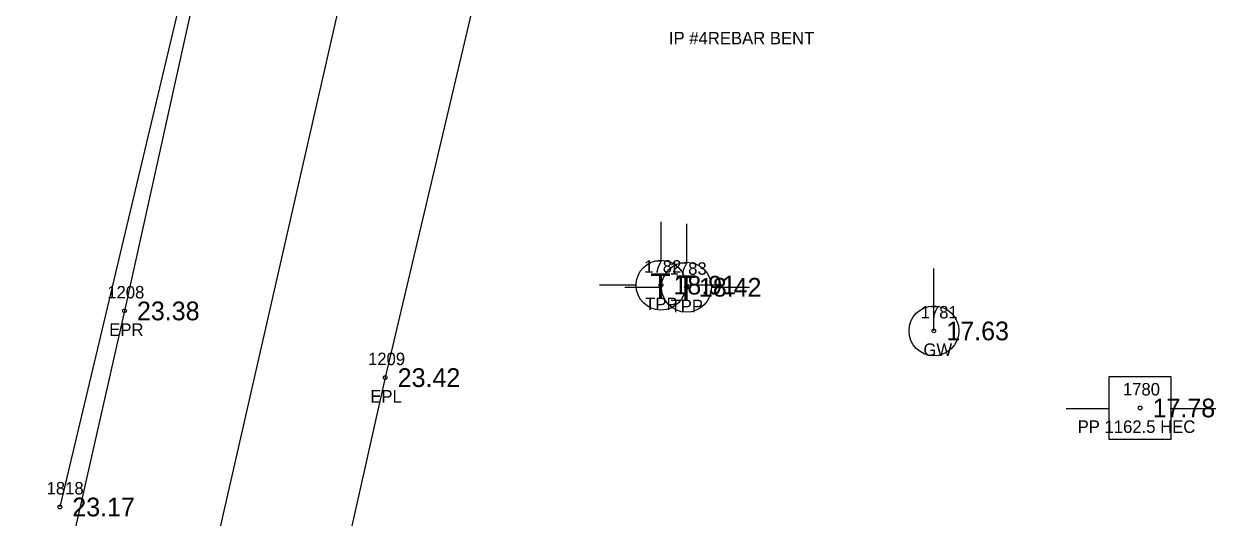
# Model space of a CAD drawing. Extents: x 2654414 to 2656963, y 761776 to 764965.
# Drawn here: x 2655685.5 to 2655781.9, y 763182 to 763221.6 of the extents above; entities that cross this region are included whole.
import ezdxf

# ---------------------------------------------------------------- set-up
doc = ezdxf.new("R2010")
doc.units = 0
for name, color, linetype in [('Default', 7, 'Continuous'), ('RD_EX_DV_Prop_txCode', 7, 'Continuous'), ('RD_EX_GuardRail', 7, 'Continuous'), ('RD_EX_GuardRail_txCode', 7, 'Continuous'), ('RD_EX_Road', 7, 'Continuous'), ('RD_EX_Road_txCode', 7, 'Continuous'), ('RD_EX_TX_GuardRail_ELEV', 7, 'Continuous'), ('RD_EX_TX_Road_ELEV', 7, 'Continuous'), ('RD_EX_TX_UT_ELEV', 7, 'Continuous'), ('RD_EX_UT', 7, 'Continuous'), ('RD_EX_UT_txCode', 7, 'Continuous'), ('RD_HC_Cl', 7, 'Continuous'), ('RD_HC_Survey_ELEV', 7, 'Continuous'), ('RD_SMD_Locator', 7, 'Continuous')]:
    doc.layers.add(name, color=color, linetype=linetype)

msp = doc.modelspace()

# ---------------------------------------------------------------- linework, layer by layer
at = {"layer": 'Default'}
msp.add_line((2656050.51, 764712.367), (2655383.263, 761787.511), dxfattribs=at)
at = {"layer": 'RD_EX_GuardRail'}
msp.add_lwpolyline([(2655721.322, 763327.656), (2655710.813, 763279.368), (2655699.76, 763230.752), (2655688.364, 763182.859)], dxfattribs=at)
at = {"layer": 'RD_EX_Road'}
for points in [[(2655700.994, 763232.279), (2655693.552, 763198.573), (2655671.649, 763102.037), (2655649.038, 763001.061), (2655627.271, 762906.233), (2655604.996, 762809.365), (2655598.992, 762783.09), (2655583.655, 762714.137), (2655561.97, 762618.323), (2655556.356, 762593.843), (2655548.114, 762557.141), (2655540.102, 762522.478), (2655518.03, 762425.04), (2655496.479, 762329.558), (2655475.552, 762236.625), (2655473.199, 762226.142), (2655466.574, 762197.504), (2655460.058, 762168.164), (2655454.261, 762143.776), (2655432.5, 762049.878), (2655410.7, 761955.515), (2655388.166, 761858.426), (2655373.501, 761793.951)], [(2655722.661, 763227.867), (2655714.474, 763193.228), (2655692.888, 763097.257), (2655670.037, 762995.178), (2655648.569, 762900.673)]]:
    msp.add_lwpolyline(points, dxfattribs=at)
at = {"layer": 'RD_EX_UT'}
for p, q in [((2655736.596, 763205.711), (2655736.596, 763202.641)), ((2655738.637, 763205.543), (2655738.637, 763202.473)), ((2655758.498, 763196.97), (2655758.498, 763201.97)), ((2655731.666, 763200.656), (2655734.596, 763200.656)), ((2655733.706, 763200.489), (2655736.637, 763200.489)), ((2655738.596, 763200.656), (2655741.666, 763200.656)), ((2655740.637, 763200.489), (2655743.706, 763200.489)), ((2655777.538, 763193.304), (2655772.538, 763193.304)), ((2655772.538, 763193.304), (2655772.538, 763188.304)), ((2655777.538, 763188.304), (2655777.538, 763193.304)), ((2655769.106, 763190.742), (2655772.576, 763190.742)), ((2655777.466, 763190.742), (2655781.106, 763190.742)), ((2655772.538, 763188.304), (2655777.538, 763188.304))]:
    msp.add_line(p, q, dxfattribs=at)
for centre, radius in [((2655736.596, 763200.641), 2), ((2655738.637, 763200.473), 2), ((2655758.498, 763196.97), 1.999)]:
    msp.add_circle(centre, radius, dxfattribs=at)
at = {"layer": 'RD_HC_Cl'}
msp.add_line((2656050.51, 764712.367), (2655383.263, 761787.511), dxfattribs=at)
at = {"layer": 'RD_SMD_Locator'}
for centre in [(2655736.596, 763200.641), (2655738.637, 763200.473), (2655693.552, 763198.573), (2655758.498, 763196.97), (2655714.474, 763193.228), (2655775.047, 763190.795), (2655688.364, 763182.859)]:
    msp.add_circle(centre, 0.15, dxfattribs=at)

# ---------------------------------------------------------------- texts
at = {"layer": 'RD_EX_DV_Prop_txCode'}
msp.add_text('IP #4REBAR BENT', height=1, dxfattribs=at).set_placement((2655737.234, 763219.942))
at = {"layer": 'RD_EX_GuardRail_txCode'}
msp.add_text('1818', height=1, dxfattribs=at).set_placement((2655687.301, 763183.859))
at = {"layer": 'RD_EX_Road_txCode'}
for s, p in [('1208', (2655692.166, 763199.573)), ('EPR', (2655692.324, 763196.573)), ('1209', (2655713.088, 763194.228)), ('EPL', (2655713.269, 763191.228))]:
    msp.add_text(s, height=1, dxfattribs=at).set_placement(p)
at = {"layer": 'RD_EX_TX_GuardRail_ELEV'}
msp.add_text('23.17', height=1.5, dxfattribs=at).set_placement((2655689.364, 763182.109))
at = {"layer": 'RD_EX_TX_Road_ELEV'}
for s, p in [('23.38', (2655694.552, 763197.823)), ('23.42', (2655715.474, 763192.478))]:
    msp.add_text(s, height=1.5, dxfattribs=at).set_placement(p)
at = {"layer": 'RD_EX_TX_UT_ELEV'}
for s, p in [('18.91', (2655737.596, 763199.891)), ('18.42', (2655739.637, 763199.723)), ('17.63', (2655759.498, 763196.22))]:
    msp.add_text(s, height=1.5, dxfattribs=at).set_placement(p)
at = {"layer": 'RD_EX_UT'}
for p in [(2655735.747, 763199.594), (2655737.788, 763199.426)]:
    msp.add_text('T', height=2, dxfattribs=at).set_placement(p)
at = {"layer": 'RD_EX_UT_txCode'}
for s, p in [('1782', (2655735.25, 763201.641)), ('1783', (2655737.291, 763201.473)), ('TPP', (2655735.328, 763198.641)), ('TPP', (2655737.369, 763198.473)), ('1781', (2655757.435, 763197.97)), ('GW', (2655757.656, 763194.97)), ('1780', (2655773.661, 763191.795)), ('PP 1162.5 HEC', (2655770.031, 763188.795))]:
    msp.add_text(s, height=1, dxfattribs=at).set_placement(p)
at = {"layer": 'RD_HC_Survey_ELEV'}
msp.add_text('17.78', height=1.5, dxfattribs=at).set_placement((2655776.047, 763190.045))

doc.saveas('drawing.dxf')
